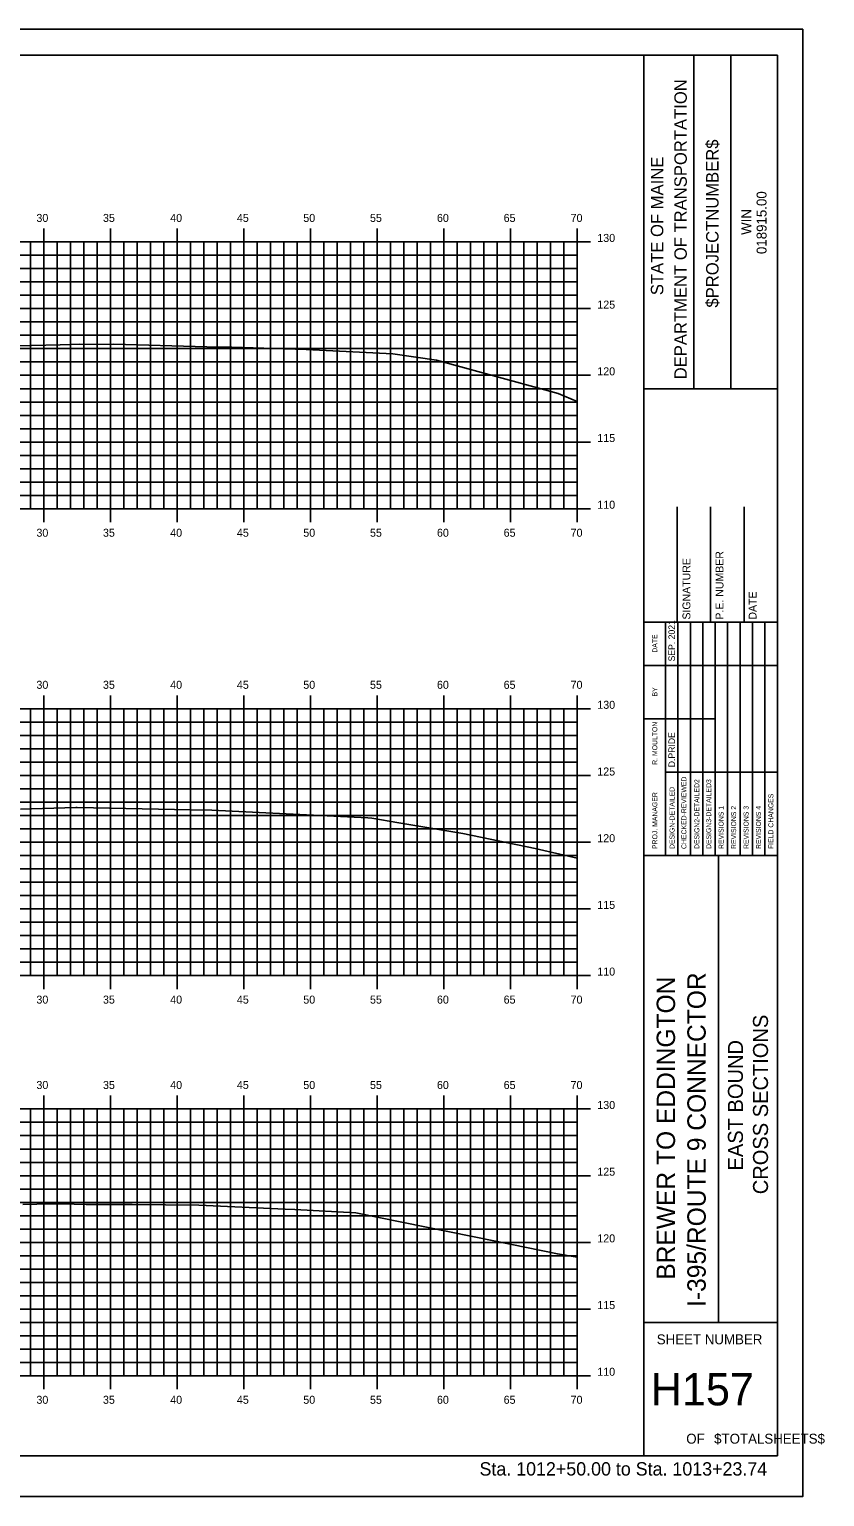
# Model space of a CAD drawing. Extents: x 852625 to 852797, y 365624 to 365734.
# Drawn here: x 852737.5 to 852797.1, y 365624 to 365734 of the extents above; entities that cross this region are included whole.
import ezdxf

# ---------------------------------------------------------------- set-up
doc = ezdxf.new("R2010")
doc.units = 0
for name, color, linetype in [('BORDER', 7, 'Continuous'), ('H_V ANNOTATION', 7, 'Continuous'), ('M_Roadway_Centerline', 7, 'Continuous'), ('MAJOR', 7, 'Continuous'), ('MINOR', 7, 'Continuous'), ('PLOT BOUNDARY', 7, 'Continuous'), ('S_Roadway_Centerline', 7, 'Continuous')]:
    doc.layers.add(name, color=color, linetype=linetype)

msp = doc.modelspace()

# ---------------------------------------------------------------- linework, layer by layer
at = {"layer": 'BORDER'}
for p, q in [((852783.55, 365627.03), (852783.55, 365732.03)), ((852787.28, 365707.02), (852787.28, 365732.02)), ((852790.07, 365707.02), (852790.07, 365732.02)), ((852783.55, 365707.02), (852793.55, 365707.02)), ((852786.05, 365689.53), (852786.05, 365698.18)), ((852788.55, 365689.53), (852788.55, 365698.18)), ((852791.05, 365689.53), (852791.05, 365698.18)), ((852783.55, 365689.53), (852793.55, 365689.53)), ((852783.55, 365672.03), (852793.55, 365672.03)), ((852789.14, 365637.03), (852789.14, 365672.03)), ((852783.55, 365637.03), (852793.55, 365637.03))]:
    msp.add_line(p, q, dxfattribs=at)
msp.add_lwpolyline([(852633.55, 365627.03), (852793.55, 365627.03), (852793.55, 365732.03), (852633.55, 365732.03)], close=True, dxfattribs=at)
for points in [[(852785.16, 365686.28), (852785.16, 365689.53)], [(852786.1, 365672.03), (852786.1, 365689.53)], [(852787.03, 365689.53), (852787.03, 365672.03)], [(852787.96, 365672.03), (852787.96, 365689.53)], [(852788.89, 365672.03), (852788.89, 365689.53)], [(852789.82, 365672.03), (852789.82, 365689.53)], [(852790.75, 365672.03), (852790.75, 365689.53)], [(852791.69, 365672.03), (852791.69, 365689.53)], [(852792.62, 365672.03), (852792.62, 365689.53)], [(852785.16, 365672.03), (852785.16, 365688.82)], [(852783.55, 365686.28), (852793.55, 365686.28)], [(852783.55, 365682.28), (852785.16, 365682.28)], [(852785.16, 365682.28), (852788.89, 365682.28)], [(852785.16, 365678.28), (852793.55, 365678.28)]]:
    msp.add_lwpolyline(points, dxfattribs=at)
at = {"layer": 'MAJOR'}
for p, q in [((852738.55, 365719.03), (852738.55, 365718.03)), ((852743.55, 365719.03), (852743.55, 365718.03)), ((852748.55, 365719.03), (852748.55, 365718.03)), ((852753.55, 365719.03), (852753.55, 365718.03)), ((852758.55, 365719.03), (852758.55, 365718.03)), ((852763.55, 365719.03), (852763.55, 365718.03)), ((852768.55, 365719.03), (852768.55, 365718.03)), ((852773.55, 365719.03), (852773.55, 365718.03)), ((852778.55, 365719.03), (852778.55, 365718.03)), ((852638.55, 365718.03), (852778.55, 365718.03)), ((852638.55, 365718.03), (852778.55, 365718.03)), ((852738.55, 365698.03), (852738.55, 365718.03)), ((852743.55, 365698.03), (852743.55, 365718.03)), ((852748.55, 365698.03), (852748.55, 365718.03)), ((852753.55, 365698.03), (852753.55, 365718.03)), ((852758.55, 365698.03), (852758.55, 365718.03)), ((852763.55, 365698.03), (852763.55, 365718.03)), ((852768.55, 365698.03), (852768.55, 365718.03)), ((852773.55, 365698.03), (852773.55, 365718.03)), ((852779.55, 365718.03), (852777.55, 365718.03)), ((852778.55, 365698.03), (852778.55, 365718.03)), ((852778.55, 365698.03), (852778.55, 365718.03)), ((852638.55, 365713.03), (852778.55, 365713.03)), ((852779.55, 365713.03), (852777.55, 365713.03)), ((852638.55, 365708.03), (852778.55, 365708.03)), ((852779.55, 365708.03), (852777.55, 365708.03)), ((852638.55, 365703.03), (852778.55, 365703.03)), ((852779.55, 365703.03), (852777.55, 365703.03)), ((852638.55, 365698.03), (852778.55, 365698.03)), ((852738.55, 365697.02), (852738.55, 365698.03)), ((852743.55, 365697.02), (852743.55, 365698.03)), ((852748.55, 365697.02), (852748.55, 365698.03)), ((852753.55, 365697.02), (852753.55, 365698.03)), ((852758.55, 365697.02), (852758.55, 365698.03)), ((852763.55, 365697.02), (852763.55, 365698.03)), ((852768.55, 365697.02), (852768.55, 365698.03)), ((852773.55, 365697.02), (852773.55, 365698.03)), ((852779.55, 365698.03), (852777.55, 365698.03)), ((852778.55, 365697.02), (852778.55, 365698.03)), ((852738.55, 365684.03), (852738.55, 365683.03)), ((852743.55, 365684.03), (852743.55, 365683.03)), ((852748.55, 365684.03), (852748.55, 365683.03)), ((852753.55, 365684.03), (852753.55, 365683.03)), ((852758.55, 365684.03), (852758.55, 365683.03)), ((852763.55, 365684.03), (852763.55, 365683.03)), ((852768.55, 365684.03), (852768.55, 365683.03)), ((852773.55, 365684.03), (852773.55, 365683.03)), ((852778.55, 365684.03), (852778.55, 365683.03)), ((852638.55, 365683.03), (852778.55, 365683.03)), ((852638.55, 365683.03), (852778.55, 365683.03)), ((852738.55, 365663.03), (852738.55, 365683.03)), ((852743.55, 365663.03), (852743.55, 365683.03)), ((852748.55, 365663.03), (852748.55, 365683.03)), ((852753.55, 365663.03), (852753.55, 365683.03)), ((852758.55, 365663.03), (852758.55, 365683.03)), ((852763.55, 365663.03), (852763.55, 365683.03)), ((852768.55, 365663.03), (852768.55, 365683.03)), ((852773.55, 365663.03), (852773.55, 365683.03)), ((852779.55, 365683.03), (852777.55, 365683.03)), ((852778.55, 365663.03), (852778.55, 365683.03)), ((852778.55, 365663.03), (852778.55, 365683.03)), ((852638.55, 365678.03), (852778.55, 365678.03)), ((852779.55, 365678.03), (852777.55, 365678.03)), ((852638.55, 365673.03), (852778.55, 365673.03)), ((852779.55, 365673.03), (852777.55, 365673.03)), ((852638.55, 365668.03), (852778.55, 365668.03)), ((852779.55, 365668.03), (852777.55, 365668.03)), ((852638.55, 365663.03), (852778.55, 365663.03)), ((852638.55, 365663.03), (852778.55, 365663.03)), ((852738.55, 365662.02), (852738.55, 365663.03)), ((852743.55, 365662.02), (852743.55, 365663.03)), ((852748.55, 365662.02), (852748.55, 365663.03)), ((852753.55, 365662.02), (852753.55, 365663.03)), ((852758.55, 365662.02), (852758.55, 365663.03)), ((852763.55, 365662.02), (852763.55, 365663.03)), ((852768.55, 365662.02), (852768.55, 365663.03)), ((852773.55, 365662.02), (852773.55, 365663.03)), ((852779.55, 365663.03), (852777.55, 365663.03)), ((852778.55, 365662.02), (852778.55, 365663.03)), ((852738.55, 365654.03), (852738.55, 365653.03)), ((852743.55, 365654.03), (852743.55, 365653.03)), ((852748.55, 365654.03), (852748.55, 365653.03)), ((852753.55, 365654.03), (852753.55, 365653.03)), ((852758.55, 365654.03), (852758.55, 365653.03)), ((852763.55, 365654.03), (852763.55, 365653.03)), ((852768.55, 365654.03), (852768.55, 365653.03)), ((852773.55, 365654.03), (852773.55, 365653.03)), ((852778.55, 365654.03), (852778.55, 365653.03)), ((852638.55, 365653.03), (852778.55, 365653.03)), ((852638.55, 365653.03), (852778.55, 365653.03)), ((852738.55, 365633.03), (852738.55, 365653.03)), ((852743.55, 365633.03), (852743.55, 365653.03)), ((852748.55, 365633.03), (852748.55, 365653.03)), ((852753.55, 365633.03), (852753.55, 365653.03)), ((852758.55, 365633.03), (852758.55, 365653.03)), ((852763.55, 365633.03), (852763.55, 365653.03)), ((852768.55, 365633.03), (852768.55, 365653.03)), ((852773.55, 365633.03), (852773.55, 365653.03)), ((852779.55, 365653.03), (852777.55, 365653.03)), ((852778.55, 365633.03), (852778.55, 365653.03)), ((852778.55, 365633.03), (852778.55, 365653.03)), ((852638.55, 365648.03), (852778.55, 365648.03)), ((852779.55, 365648.03), (852777.55, 365648.03)), ((852638.55, 365643.03), (852778.55, 365643.03)), ((852779.55, 365643.03), (852777.55, 365643.03)), ((852638.55, 365638.03), (852778.55, 365638.03)), ((852779.55, 365638.03), (852777.55, 365638.03)), ((852638.55, 365633.03), (852778.55, 365633.03)), ((852638.55, 365633.03), (852778.55, 365633.03)), ((852738.55, 365632.02), (852738.55, 365633.03)), ((852743.55, 365632.02), (852743.55, 365633.03)), ((852748.55, 365632.02), (852748.55, 365633.03)), ((852753.55, 365632.02), (852753.55, 365633.03)), ((852758.55, 365632.02), (852758.55, 365633.03)), ((852763.55, 365632.02), (852763.55, 365633.03)), ((852768.55, 365632.02), (852768.55, 365633.03)), ((852773.55, 365632.02), (852773.55, 365633.03)), ((852779.55, 365633.03), (852777.55, 365633.03)), ((852778.55, 365632.02), (852778.55, 365633.03))]:
    msp.add_line(p, q, dxfattribs=at)
at = {"layer": 'MINOR'}
for p, q in [((852638.55, 365717.03), (852778.55, 365717.03)), ((852737.55, 365698.03), (852737.55, 365718.03)), ((852739.55, 365698.03), (852739.55, 365718.03)), ((852740.55, 365698.03), (852740.55, 365718.03)), ((852741.55, 365698.03), (852741.55, 365718.03)), ((852742.55, 365698.03), (852742.55, 365718.03)), ((852744.55, 365698.03), (852744.55, 365718.03)), ((852745.55, 365698.03), (852745.55, 365718.03)), ((852746.55, 365698.03), (852746.55, 365718.03)), ((852747.55, 365698.03), (852747.55, 365718.03)), ((852749.55, 365698.03), (852749.55, 365718.03)), ((852750.55, 365698.03), (852750.55, 365718.03)), ((852751.55, 365698.03), (852751.55, 365718.03)), ((852752.55, 365698.03), (852752.55, 365718.03)), ((852754.55, 365698.03), (852754.55, 365718.03)), ((852755.55, 365698.03), (852755.55, 365718.03)), ((852756.55, 365698.03), (852756.55, 365718.03)), ((852757.55, 365698.03), (852757.55, 365718.03)), ((852759.55, 365698.03), (852759.55, 365718.03)), ((852760.55, 365698.03), (852760.55, 365718.03)), ((852761.55, 365698.03), (852761.55, 365718.03)), ((852762.55, 365698.03), (852762.55, 365718.03)), ((852764.55, 365698.03), (852764.55, 365718.03)), ((852765.55, 365698.03), (852765.55, 365718.03)), ((852766.55, 365698.03), (852766.55, 365718.03)), ((852767.55, 365698.03), (852767.55, 365718.03)), ((852769.55, 365698.03), (852769.55, 365718.03)), ((852770.55, 365698.03), (852770.55, 365718.03)), ((852771.55, 365698.03), (852771.55, 365718.03)), ((852772.55, 365698.03), (852772.55, 365718.03)), ((852774.55, 365698.03), (852774.55, 365718.03)), ((852775.55, 365698.03), (852775.55, 365718.03)), ((852776.55, 365698.03), (852776.55, 365718.03)), ((852777.55, 365698.03), (852777.55, 365718.03)), ((852778.55, 365717.03), (852777.55, 365717.03)), ((852638.55, 365716.03), (852778.55, 365716.03)), ((852778.55, 365716.03), (852777.55, 365716.03)), ((852638.55, 365715.03), (852778.55, 365715.03)), ((852778.55, 365715.03), (852777.55, 365715.03)), ((852638.55, 365714.03), (852778.55, 365714.03)), ((852778.55, 365714.03), (852777.55, 365714.03)), ((852638.55, 365712.03), (852778.55, 365712.03)), ((852778.55, 365712.03), (852777.55, 365712.03)), ((852638.55, 365711.03), (852778.55, 365711.03)), ((852778.55, 365711.03), (852777.55, 365711.03)), ((852638.55, 365710.03), (852778.55, 365710.03)), ((852778.55, 365710.03), (852777.55, 365710.03)), ((852638.55, 365709.03), (852778.55, 365709.03)), ((852778.55, 365709.03), (852777.55, 365709.03)), ((852638.55, 365707.03), (852778.55, 365707.03)), ((852638.55, 365706.03), (852778.55, 365706.03)), ((852778.55, 365707.03), (852777.55, 365707.03)), ((852778.55, 365706.03), (852777.55, 365706.03)), ((852638.55, 365705.03), (852778.55, 365705.03)), ((852778.55, 365705.03), (852777.55, 365705.03)), ((852638.55, 365704.03), (852778.55, 365704.03)), ((852778.55, 365704.03), (852777.55, 365704.03)), ((852638.55, 365702.03), (852778.55, 365702.03)), ((852778.55, 365702.03), (852777.55, 365702.03)), ((852638.55, 365701.03), (852778.55, 365701.03)), ((852778.55, 365701.03), (852777.55, 365701.03)), ((852638.55, 365700.03), (852778.55, 365700.03)), ((852778.55, 365700.03), (852777.55, 365700.03)), ((852638.55, 365699.03), (852778.55, 365699.03)), ((852778.55, 365699.03), (852777.55, 365699.03)), ((852737.55, 365663.03), (852737.55, 365683.03)), ((852739.55, 365663.03), (852739.55, 365683.03)), ((852740.55, 365663.03), (852740.55, 365683.03)), ((852741.55, 365663.03), (852741.55, 365683.03)), ((852742.55, 365663.03), (852742.55, 365683.03)), ((852744.55, 365663.03), (852744.55, 365683.03)), ((852745.55, 365663.03), (852745.55, 365683.03)), ((852746.55, 365663.03), (852746.55, 365683.03)), ((852747.55, 365663.03), (852747.55, 365683.03)), ((852749.55, 365663.03), (852749.55, 365683.03)), ((852750.55, 365663.03), (852750.55, 365683.03)), ((852751.55, 365663.03), (852751.55, 365683.03)), ((852752.55, 365663.03), (852752.55, 365683.03)), ((852754.55, 365663.03), (852754.55, 365683.03)), ((852755.55, 365663.03), (852755.55, 365683.03)), ((852756.55, 365663.03), (852756.55, 365683.03)), ((852757.55, 365663.03), (852757.55, 365683.03)), ((852759.55, 365663.03), (852759.55, 365683.03)), ((852760.55, 365663.03), (852760.55, 365683.03)), ((852761.55, 365663.03), (852761.55, 365683.03)), ((852762.55, 365663.03), (852762.55, 365683.03)), ((852764.55, 365663.03), (852764.55, 365683.03)), ((852765.55, 365663.03), (852765.55, 365683.03)), ((852766.55, 365663.03), (852766.55, 365683.03)), ((852767.55, 365663.03), (852767.55, 365683.03)), ((852769.55, 365663.03), (852769.55, 365683.03)), ((852770.55, 365663.03), (852770.55, 365683.03)), ((852771.55, 365663.03), (852771.55, 365683.03)), ((852772.55, 365663.03), (852772.55, 365683.03)), ((852774.55, 365663.03), (852774.55, 365683.03)), ((852775.55, 365663.03), (852775.55, 365683.03)), ((852776.55, 365663.03), (852776.55, 365683.03)), ((852777.55, 365663.03), (852777.55, 365683.03)), ((852638.55, 365682.03), (852778.55, 365682.03)), ((852778.55, 365682.03), (852777.55, 365682.03)), ((852638.55, 365681.03), (852778.55, 365681.03)), ((852778.55, 365681.03), (852777.55, 365681.03)), ((852638.55, 365680.03), (852778.55, 365680.03)), ((852778.55, 365680.03), (852777.55, 365680.03)), ((852638.55, 365679.03), (852778.55, 365679.03)), ((852778.55, 365679.03), (852777.55, 365679.03)), ((852638.55, 365677.03), (852778.55, 365677.03)), ((852778.55, 365677.03), (852777.55, 365677.03)), ((852638.55, 365676.03), (852778.55, 365676.03)), ((852778.55, 365676.03), (852777.55, 365676.03)), ((852638.55, 365675.03), (852778.55, 365675.03)), ((852778.55, 365675.03), (852777.55, 365675.03)), ((852638.55, 365674.03), (852778.55, 365674.03)), ((852778.55, 365674.03), (852777.55, 365674.03)), ((852638.55, 365672.03), (852778.55, 365672.03)), ((852778.55, 365672.03), (852777.55, 365672.03)), ((852638.55, 365671.03), (852778.55, 365671.03)), ((852778.55, 365671.03), (852777.55, 365671.03)), ((852638.55, 365670.03), (852778.55, 365670.03)), ((852778.55, 365670.03), (852777.55, 365670.03)), ((852638.55, 365669.03), (852778.55, 365669.03)), ((852778.55, 365669.03), (852777.55, 365669.03)), ((852638.55, 365667.03), (852778.55, 365667.03)), ((852778.55, 365667.03), (852777.55, 365667.03)), ((852638.55, 365666.03), (852778.55, 365666.03)), ((852778.55, 365666.03), (852777.55, 365666.03)), ((852638.55, 365665.03), (852778.55, 365665.03)), ((852778.55, 365665.03), (852777.55, 365665.03)), ((852638.55, 365664.03), (852778.55, 365664.03)), ((852778.55, 365664.03), (852777.55, 365664.03)), ((852737.55, 365633.03), (852737.55, 365653.03)), ((852739.55, 365633.03), (852739.55, 365653.03)), ((852740.55, 365633.03), (852740.55, 365653.03)), ((852741.55, 365633.03), (852741.55, 365653.03)), ((852742.55, 365633.03), (852742.55, 365653.03)), ((852744.55, 365633.03), (852744.55, 365653.03)), ((852745.55, 365633.03), (852745.55, 365653.03)), ((852746.55, 365633.03), (852746.55, 365653.03)), ((852747.55, 365633.03), (852747.55, 365653.03)), ((852749.55, 365633.03), (852749.55, 365653.03)), ((852750.55, 365633.03), (852750.55, 365653.03)), ((852751.55, 365633.03), (852751.55, 365653.03)), ((852752.55, 365633.03), (852752.55, 365653.03)), ((852754.55, 365633.03), (852754.55, 365653.03)), ((852755.55, 365633.03), (852755.55, 365653.03)), ((852756.55, 365633.03), (852756.55, 365653.03)), ((852757.55, 365633.03), (852757.55, 365653.03)), ((852759.55, 365633.03), (852759.55, 365653.03)), ((852760.55, 365633.03), (852760.55, 365653.03)), ((852761.55, 365633.03), (852761.55, 365653.03)), ((852762.55, 365633.03), (852762.55, 365653.03)), ((852764.55, 365633.03), (852764.55, 365653.03)), ((852765.55, 365633.03), (852765.55, 365653.03)), ((852766.55, 365633.03), (852766.55, 365653.03)), ((852767.55, 365633.03), (852767.55, 365653.03)), ((852769.55, 365633.03), (852769.55, 365653.03)), ((852770.55, 365633.03), (852770.55, 365653.03)), ((852771.55, 365633.03), (852771.55, 365653.03)), ((852772.55, 365633.03), (852772.55, 365653.03)), ((852774.55, 365633.03), (852774.55, 365653.03)), ((852775.55, 365633.03), (852775.55, 365653.03)), ((852776.55, 365633.03), (852776.55, 365653.03)), ((852777.55, 365633.03), (852777.55, 365653.03)), ((852638.55, 365652.03), (852778.55, 365652.03)), ((852638.55, 365651.03), (852778.55, 365651.03)), ((852778.55, 365652.03), (852777.55, 365652.03)), ((852778.55, 365651.03), (852777.55, 365651.03)), ((852638.55, 365650.03), (852778.55, 365650.03)), ((852778.55, 365650.03), (852777.55, 365650.03)), ((852638.55, 365649.03), (852778.55, 365649.03)), ((852778.55, 365649.03), (852777.55, 365649.03)), ((852638.55, 365647.03), (852778.55, 365647.03)), ((852778.55, 365647.03), (852777.55, 365647.03)), ((852638.55, 365646.03), (852778.55, 365646.03)), ((852778.55, 365646.03), (852777.55, 365646.03)), ((852638.55, 365645.03), (852778.55, 365645.03)), ((852778.55, 365645.03), (852777.55, 365645.03)), ((852638.55, 365644.03), (852778.55, 365644.03)), ((852778.55, 365644.03), (852777.55, 365644.03)), ((852638.55, 365642.03), (852778.55, 365642.03)), ((852778.55, 365642.03), (852777.55, 365642.03)), ((852638.55, 365641.03), (852778.55, 365641.03)), ((852638.55, 365640.03), (852778.55, 365640.03)), ((852778.55, 365641.03), (852777.55, 365641.03)), ((852778.55, 365640.03), (852777.55, 365640.03)), ((852638.55, 365639.03), (852778.55, 365639.03)), ((852778.55, 365639.03), (852777.55, 365639.03)), ((852638.55, 365637.03), (852778.55, 365637.03)), ((852778.55, 365637.03), (852777.55, 365637.03)), ((852638.55, 365636.03), (852778.55, 365636.03)), ((852778.55, 365636.03), (852777.55, 365636.03)), ((852638.55, 365635.03), (852778.55, 365635.03)), ((852778.55, 365635.03), (852777.55, 365635.03)), ((852638.55, 365634.03), (852778.55, 365634.03)), ((852778.55, 365634.03), (852777.55, 365634.03))]:
    msp.add_line(p, q, dxfattribs=at)
at = {"layer": 'PLOT BOUNDARY'}
msp.add_lwpolyline([(852625.46, 365623.97), (852795.46, 365623.97), (852795.46, 365733.97), (852625.46, 365733.97)], close=True, dxfattribs=at)
at = {"layer": 'S_Roadway_Centerline'}
for points in [[(852733.32, 365710.17), (852739.79, 365710.32), (852741.26, 365710.37), (852742.58, 365710.34), (852743.8, 365710.36), (852750.78, 365710.17), (852752.66, 365710.14), (852758.23, 365709.96), (852764.72, 365709.65), (852768, 365709.16), (852777.12, 365706.66), (852778.55, 365706.08)], [(852736.8, 365675.51), (852740.95, 365675.63), (852741.06, 365675.63), (852749.58, 365675.46), (852751.14, 365675.42), (852757.76, 365675.1), (852762.84, 365674.85), (852763.14, 365674.84), (852765.18, 365674.49), (852769.96, 365673.67), (852775.4, 365672.55), (852778.55, 365671.84)], [(852736.97, 365645.86), (852738.03, 365645.89), (852739.94, 365645.91), (852741.72, 365645.88), (852745.18, 365645.88), (852750.17, 365645.81), (852756.64, 365645.53), (852757.37, 365645.49), (852761.95, 365645.24), (852772.43, 365643.12), (852777.06, 365642.17), (852778.55, 365641.92)]]:
    msp.add_lwpolyline(points, dxfattribs=at)

# ---------------------------------------------------------------- texts
at = {"layer": 'BORDER'}
for s, height, p in [('DEPARTMENT OF TRANSPORTATION', 0.9318, (852786.76, 365707.73)), ('$PROJECTNUMBER$', 0.9318, (852789.14, 365713.11)), ('STATE OF MAINE', 0.9318, (852785, 365714.04)), ('018915.00', 0.745, (852792.74, 365717.12)), ('WIN', 0.745, (852791.59, 365718.56)), ('SIGNATURE', 0.591, (852787.03, 365689.72)), ('P.E. NUMBER', 0.5906, (852789.51, 365689.72)), ('DATE', 0.591, (852791.99, 365689.72)), ('SEP. 2021', 0.485, (852785.87, 365686.58)), ('DATE', 0.371, (852784.55, 365687.24)), ('BY', 0.371, (852784.55, 365683.96)), ('R. MOULTON', 0.373, (852784.55, 365678.83)), ('D.PRIDE', 0.485, (852785.87, 365678.65)), ('CHECKED-REVIEWED', 0.3727, (852786.73, 365672.52)), ('DESIGN2-DETAILED2', 0.3727, (852787.7, 365672.52)), ('DESIGN3-DETAILED3', 0.3727, (852788.59, 365672.52)), ('PROJ. MANAGER', 0.3727, (852784.55, 365672.52)), ('DESIGN-DETAILED', 0.3727, (852785.84, 365672.52)), ('FIELD CHANGES', 0.3727, (852793.25, 365672.52)), ('REVISIONS 1', 0.3727, (852789.52, 365672.52)), ('REVISIONS 2', 0.3727, (852790.46, 365672.52)), ('REVISIONS 3', 0.3727, (852791.39, 365672.52)), ('REVISIONS 4', 0.3727, (852792.32, 365672.52)), ('I-395/ROUTE 9 CONNECTOR', 1.3779, (852788.18, 365638.19)), ('BREWER TO EDDINGTON', 1.3779, (852785.88, 365640.23)), ('CROSS SECTIONS', 1.125, (852792.85, 365646.64)), ('EAST BOUND', 1.125, (852790.97, 365648.42))]:
    msp.add_text(s, height=height, rotation=90, dxfattribs=at).set_placement(p)
for s, height, p in [('SHEET NUMBER', 0.7453, (852784.51, 365635.39)), ('H157', 2.419, (852784.06, 365630.81)), ('OF', 0.745, (852786.72, 365627.94)), ('$TOTALSHEETS$', 0.7453, (852788.81, 365627.94))]:
    msp.add_text(s, height=height, dxfattribs=at).set_placement(p)
at = {"layer": 'H_V ANNOTATION'}
for s, height, p in [('30', 0.6, (852738, 365719.53)), ('35', 0.6, (852742.99, 365719.53)), ('40', 0.6, (852748.03, 365719.53)), ('45', 0.6, (852753.03, 365719.53)), ('50', 0.6, (852758.01, 365719.53)), ('55', 0.6, (852763.01, 365719.53)), ('60', 0.6, (852768.03, 365719.53)), ('65', 0.6, (852773.03, 365719.53)), ('70', 0.6, (852778.05, 365719.53)), ('130', 0.6, (852780.05, 365718.03)), ('125', 0.6, (852780.05, 365713.03)), ('120', 0.6, (852780.05, 365708.03)), ('115', 0.6, (852780.05, 365703.03)), ('110', 0.6, (852780.05, 365698.03)), ('30', 0.6, (852738, 365695.93)), ('35', 0.6, (852742.99, 365695.93)), ('40', 0.6, (852748.03, 365695.93)), ('45', 0.6, (852753.03, 365695.93)), ('50', 0.6, (852758.01, 365695.93)), ('55', 0.6, (852763.01, 365695.93)), ('60', 0.6, (852768.03, 365695.93)), ('65', 0.6, (852773.03, 365695.93)), ('70', 0.6, (852778.05, 365695.93)), ('30', 0.6, (852738, 365684.53)), ('35', 0.6, (852742.99, 365684.53)), ('40', 0.6, (852748.03, 365684.53)), ('45', 0.6, (852753.03, 365684.53)), ('50', 0.6, (852758.01, 365684.53)), ('55', 0.6, (852763.01, 365684.53)), ('60', 0.6, (852768.03, 365684.53)), ('65', 0.6, (852773.03, 365684.53)), ('70', 0.6, (852778.05, 365684.53)), ('130', 0.6, (852780.05, 365683.03)), ('125', 0.6, (852780.05, 365678.03)), ('120', 0.6, (852780.05, 365673.03)), ('115', 0.6, (852780.05, 365668.03)), ('110', 0.6, (852780.05, 365663.03)), ('30', 0.6, (852738, 365660.93)), ('35', 0.6, (852742.99, 365660.93)), ('40', 0.6, (852748.03, 365660.93)), ('45', 0.6, (852753.03, 365660.93)), ('50', 0.6, (852758.01, 365660.93)), ('55', 0.6, (852763.01, 365660.93)), ('60', 0.6, (852768.03, 365660.93)), ('65', 0.6, (852773.03, 365660.93)), ('70', 0.6, (852778.05, 365660.93)), ('30', 0.6, (852738, 365654.53)), ('35', 0.6, (852742.99, 365654.53)), ('40', 0.6, (852748.03, 365654.53)), ('45', 0.6, (852753.03, 365654.53)), ('50', 0.6, (852758.01, 365654.53)), ('55', 0.6, (852763.01, 365654.53)), ('60', 0.6, (852768.03, 365654.53)), ('65', 0.6, (852773.03, 365654.53)), ('70', 0.6, (852778.05, 365654.53)), ('130', 0.6, (852780.05, 365653.03)), ('125', 0.6, (852780.05, 365648.03)), ('120', 0.6, (852780.05, 365643.03)), ('115', 0.6, (852780.05, 365638.03)), ('110', 0.6, (852780.05, 365633.03)), ('30', 0.6, (852738, 365630.93)), ('35', 0.6, (852742.99, 365630.93)), ('40', 0.6, (852748.03, 365630.93)), ('45', 0.6, (852753.03, 365630.93)), ('50', 0.6, (852758.01, 365630.93)), ('55', 0.6, (852763.01, 365630.93)), ('60', 0.6, (852768.03, 365630.93)), ('65', 0.6, (852773.03, 365630.93)), ('70', 0.6, (852778.05, 365630.93)), ('Sta. 1012+50.00 to Sta. 1013+23.74', 1.0002, (852771.22, 365625.55))]:
    msp.add_text(s, height=height, dxfattribs=at).set_placement(p)
at = {"layer": 'M_Roadway_Centerline'}
for s, p in [('C', (852740.95, 365675.63)), ('L', (852740.95, 365675.62)), ('C', (852739.93, 365645.91)), ('L', (852739.94, 365645.91))]:
    msp.add_text(s, height=0.0146, dxfattribs=at).set_placement(p)

doc.saveas('drawing.dxf')
